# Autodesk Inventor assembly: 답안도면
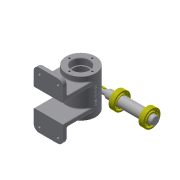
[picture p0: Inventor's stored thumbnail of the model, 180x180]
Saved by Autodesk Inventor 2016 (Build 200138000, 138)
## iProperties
Created: 2017-02
Part Number: 답안도면
Material: 일반
Document SubType Name: Assembly
Designer: CAMTIC
Author: CAMTIC
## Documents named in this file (5)
- C:\Users\CAMTIC\Desktop\470207V1017\답안도면.iam
- C:\Users\CAMTIC\Desktop\470207V1017\본체.ipt
- C:\Users\CAMTIC\Desktop\470207V1017\470207V1017\축.ipt
- C:\Users\CAMTIC\Desktop\470207V1017\470207V1017\키 3 x 3 x 12.ipt
- C:\Users\CAMTIC\Desktop\470207V1017\470207V1017\베어링 15 x 32 x 9.ipt
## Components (2 placed, 1 different names)
1. KS B 2023 6002 - 15 x 32 x 9:1
2. KS B 2023 6002 - 15 x 32 x 9:2
